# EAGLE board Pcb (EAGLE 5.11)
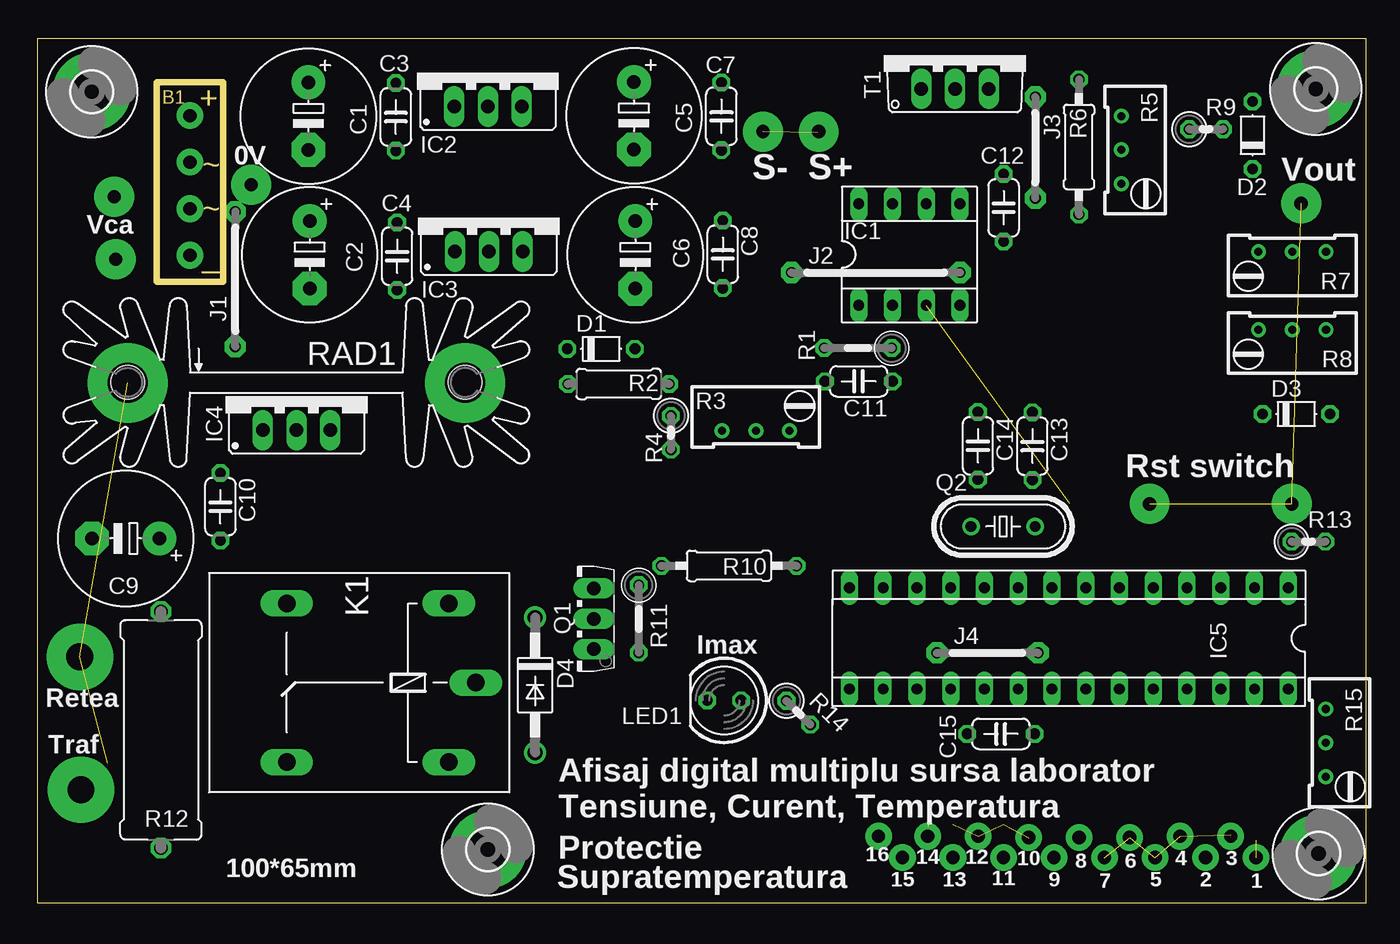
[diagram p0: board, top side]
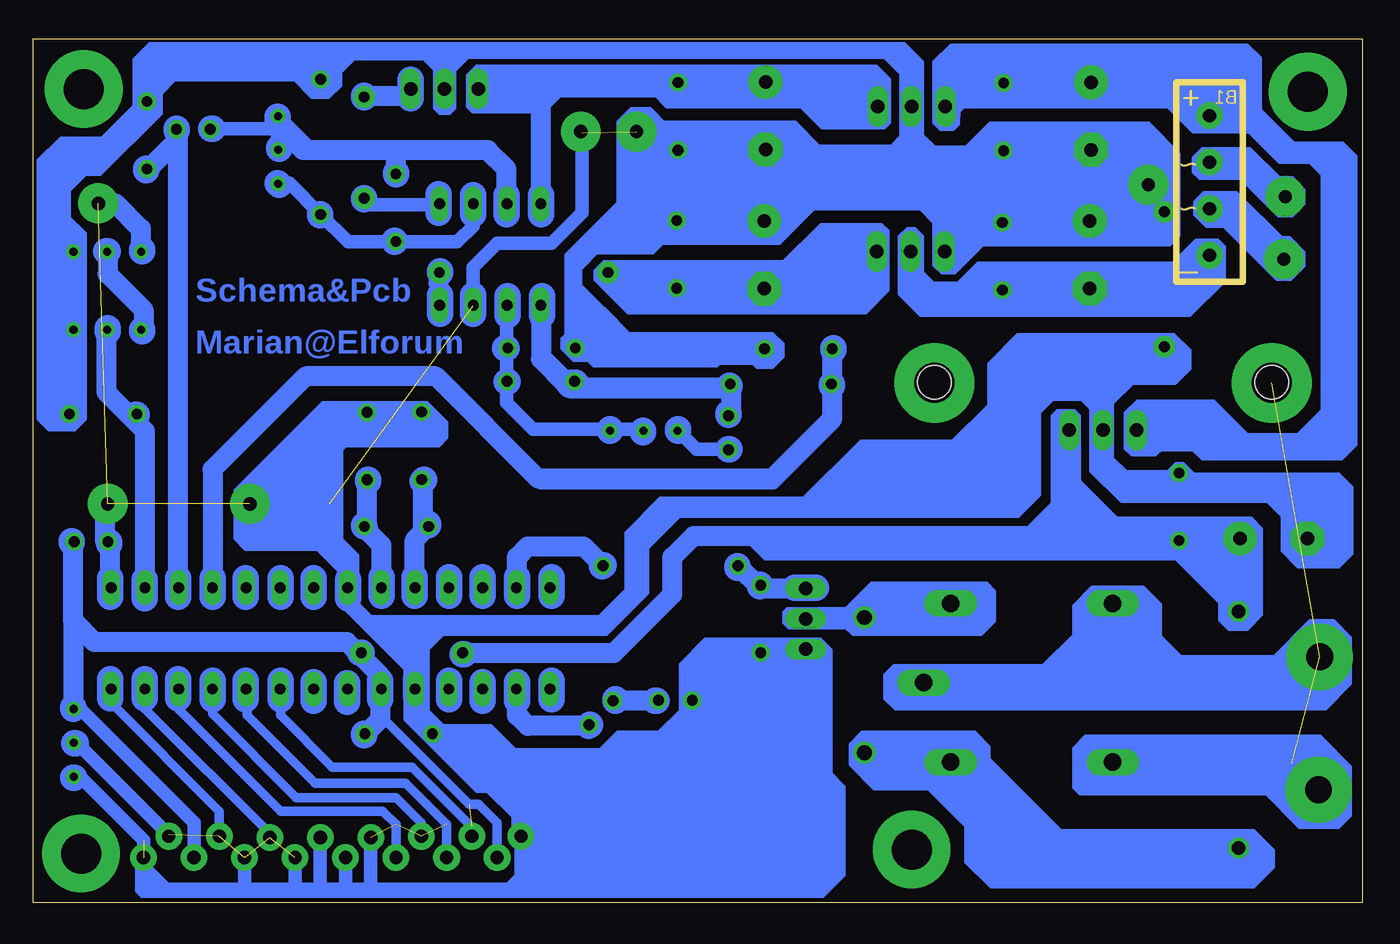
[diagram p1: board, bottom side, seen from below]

Size 100 x 65 mm. Coordinates in mm from the lower left corner, seen from the top.
Outline: 0,0 100,0 100,65 0,65 0,0
Outline: 9,61.7 14,61.7 14,46.7 9,46.7 9,61.7
Copper layers (1*16): Top 0.035mm / dielectric 1.5mm / Bottom 0.035mm
Design rules "default": minimum track width 10mil, minimum drill 24mil, track to track 8mil, track to pad 8mil, pad to pad 8mil, via to via 8mil, smd to smd 8mil, copper to edge 40mil, drill to drill 8mil, minimum pad ring 10mil, minimum via ring 8mil, stop-mask expansion 4mil, vias tented up to drill 0mil, thermal gap 10mil

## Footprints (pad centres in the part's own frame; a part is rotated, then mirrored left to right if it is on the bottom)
E5-10,5 = drill 1.016 pad 2.54 round: + -2.54,0 | drill 1.016 pad 2.54 octagon: - 2.54,0
C050-024X044 = drill 0.813 octagon: 1 -2.54,0; 2 2.54,0
D-5 = drill 0.813 octagon: A 2.54,0; C -2.54,0
DO41-10 = drill 1.118 round: A 5.08,0; C -5.08,0
3,0-PAD = drill 3 pad 5.842 round: B3,0 0,0
SOCKET-08 = drill 0.813 long: 1 -3.81,-3.81; 2 -1.27,-3.81; 3 1.27,-3.81; 4 3.81,-3.81; 5 3.81,3.81; 6 1.27,3.81; 7 -1.27,3.81; 8 -3.81,3.81
78XXS = drill 1.016 long: GND 0,-2.54; IN -2.54,-2.54; OUT 2.54,-2.54
79XXS = drill 1.016 long: GND -2.54,-2.54; IN 0,-2.54; OUT 2.54,-2.54
SOCKET-28-3 = drill 0.813 long: 1 -16.51,-3.81; 2 -13.97,-3.81; 3 -11.43,-3.81; 4 -8.89,-3.81; 5 -6.35,-3.81; 6 -3.81,-3.81; 7 -1.27,-3.81; 8 1.27,-3.81; 9 3.81,-3.81; 10 6.35,-3.81; 11 8.89,-3.81; 12 11.43,-3.81; 13 13.97,-3.81; 14 16.51,-3.81; 15 16.51,3.81; 16 13.97,3.81; 17 11.43,3.81; 18 8.89,3.81; 19 6.35,3.81; 20 3.81,3.81; 21 1.27,3.81; 22 -1.27,3.81; 23 -3.81,3.81; 24 -6.35,3.81; 25 -8.89,3.81; 26 -11.43,3.81; 27 -13.97,3.81; 28 -16.51,3.81
10 = drill 0.813 pad 1.6 octagon: 1 -5.08,0; 2 5.08,0
12 = drill 0.813 pad 1.6 octagon: 1 -6.35,0; 2 6.35,0
07 = drill 0.813 pad 1.6 octagon: 1 -3.81,0; 2 3.81,0
G5LE = drill 1.321 long: 1 -7.493,-5.969; 2 -7.493,5.969; O 4.699,5.969; P -9.525,0; S 4.699,-5.969
LED5MM = drill 0.813 octagon: A -1.27,0; K 1.27,0
TO126V = drill 1.016 long: 1 -2.286,-1.27; 2 0,-1.27; 3 2.286,-1.27
HC49/S = drill 0.813 round: 1 -2.413,0; 2 2.413,0
0207/5V = drill 0.813 octagon: 1 -2.54,0; 2 2.54,0
0207/7 = drill 0.813 octagon: 1 -3.81,0; 2 3.81,0
RTRIM64W = drill 0.61 round: 1 1.27,-2.54; 2 1.27,0; 3 1.27,2.54
0207/2V = drill 0.813 octagon: 1 -1.27,0; 2 1.27,0
0207/10 = drill 0.813 octagon: 1 -5.08,0; 2 5.08,0
0617/17 = drill 1.016 octagon: 1 -8.89,0; 2 8.89,0
SK104 = hole 2.54: -12.7,-0.762; 12.7,-0.762
TO220AV = drill 1.016 long: B -2.54,-2.54; C 0,-2.54; E 2.54,-2.54

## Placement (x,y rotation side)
C1  [E5-10,5]  20.4,59.17 270 top
C2  220u  [E5-10,5]  20.5,48.74 270 top
C3  220n  [C050-024X044]  26.98,59.11 270 top
C4  220n  [C050-024X044]  27.08,48.63 270 top
C5  100u  [E5-10,5]  44.9,59.2 270 top
C6  100u  [E5-10,5]  45,48.73 270 top
C7  100n  [C050-024X044]  51.48,59.15 270 top
C8  100n  [C050-024X044]  51.58,48.77 270 top
C9  100u  [E5-10,5]  6.66,27.4 180 top
C10  100n  [C050-024X044]  13.78,29.79 270 top
C11  1n  [C050-024X044]  61.81,39.22 180 top
C12  1n  [C050-024X044]  72.72,52.27 90 top
C13  22p  [C050-024X044]  74.88,34.35 270 top
C14  22p  [C050-024X044]  70.78,34.37 270 top
C15  470n  [C050-024X044]  72.51,12.7 180 top
D1  5V1  [D-5]  42.43,41.66 0 top
D2  5V1  [D-5]  91.44,57.73 90 top
D3  5V1  [D-5]  94.73,36.76 0 top
D4  1N4004  [DO41-10]  37.46,16.37 270 top
E$1  [3,0-PAD]  96.2,61.2 0 top
E$2  [3,0-PAD]  96.4,3.7 0 top
E$3  [3,0-PAD]  33.9,4 0 top
E$4  [3,0-PAD]  4.1,61 0 top
IC1  LM358  [SOCKET-08]  65.62,48.76 0 top
IC2  7808  [78XXS]  33.91,62.43 0 top
IC3  7908  [79XXS]  33.98,51.53 0 top
IC4  7805  [78XXS]  19.51,38.08 0 top
IC5  PIC16F876A  [SOCKET-28-3]  77.62,19.89 180 top
J1  [10]  14.9,46.9 90 top
J2  [12]  63.1,47.4 0 top
J3  [07]  75.1,56.8 270 top
J4  [07]  71.5,18.8 0 top
K1  3V  [G5LE]  23.47,16.55 180 top
LED1  [LED5MM]  51.69,15.22 180 top
Q1  BD139-16  [TO126V]  40.61,21.36 90 top
Q2  4Mhz  [HC49/S]  72.67,28.3 0 top
R1  1k  [0207/5V]  61.75,41.72 180 top
R2  470  [0207/7]  43.75,39.02 180 top
R3  20k  [RTRIM64W]  54.07,36.78 270 top
R4  1k  [0207/2V]  47.68,35.35 270 top
R5  5k  [RTRIM64W]  82.84,56.63 180 top
R6  1k  [0207/10]  78.38,56.85 270 top
R7  100k  [RTRIM64W]  94.43,47.7 90 top
R8  10k  [RTRIM64W]  94.43,41.84 90 top
R9  470  [0207/2V]  87.95,58.18 0 top
R10  1k  [0207/10]  52.05,25.34 180 top
R11  10k  [0207/5V]  45.26,21.35 270 top
R12  20R/3W  [0617/17]  9.31,13.01 90 top
R13  10k  [0207/2V]  95.65,27.16 0 top
R14  220  [0207/2V]  57.27,14.29 315 top
R15  1k  [RTRIM64W]  98.22,12.03 180 top
RAD1  [SK104]  19.5,39.9 0 top
T1  LM35DT  [TO220AV]  69.05,63.76 0 top

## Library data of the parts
C1-C15 R1-R11 R13-R15 = resistor
D1-D4 = diode
E$1-E$4 = holes
IC1 = ic-package
IC2-IC4 = v-reg
IC5 = ic-package; OC_FARNELL: unknown; OC_NEWARK: unknown
J1-J4 = jumper
K1 = relay; OC_FARNELL: unknown; OC_NEWARK: unknown
LED1 = led
Q1 = transistor-npn
Q2 = crystal; OC_FARNELL: 1667008; OC_NEWARK: unknown
R12 = resistor; OC_FARNELL: unknown; OC_NEWARK: unknown
RAD1 = heatsink
T1 = transistor-power

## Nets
N$15: R7.3
N$26: K1.1
S$106: C9.+

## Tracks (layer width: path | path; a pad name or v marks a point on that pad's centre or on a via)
S$1  (via drill 1 pad 2)
  other vias: 11.5,59.2
S$2
  Bottom 0.5: 12,56.6 12.6,56 12.6,55 12.2,54.6 9.1,54.6 6.3,51.8 5.3,51.8 4.5,52.6 4.5,53.6 5.3,54.4 6.3,54.4 8.5,56.6 12,56.6
S$3
  Bottom 0.5: 35.7,58.7 35.7,61.9 36.6,62.8 66.6,62.8 67.2,62.2 67.2,59.9 66.9,59.6 61.6,59.6 60.4,60.8 53.1,60.8 52.3,60 42.2,60 40.6,58.4 36,58.4 35.7,58.7
S$4  (via drill 1 pad 2)
  other vias: 11.5,48.7
S$5
  Bottom 0.5: 27,51.4 27.1,51.3
S$6  (via drill 2 pad 5)
  other vias: 3.3,8.5
S$7  (via drill 1 pad 2)
  other vias: 11.5,55.7
S$8
  Bottom 0.5: 32.3,46.5 33.2,47.4 33.2,50.1 33.7,50.6 34.2,50.6 34.7,50.1 34.7,45.8 33.2,44.3 13,44.3 10.5,46.8 10.5,49.3 10.9,49.7 12.5,49.7 14.2,48 28.9,48 30.4,46.5 32.3,46.5
S$9  (via drill 1 pad 3)
  other vias: 5.9,48.4
S$10  (via drill 1 pad 3)
  other vias: 5.8,53.1
S$11
  Bottom 0.5: 35.8,46.1 35.8,50.5 36.2,50.9 40.7,50.9 43.5,48.1 57,48.1 57.6,47.5 57.6,46.9 55.2,44.5 37.4,44.5 35.8,46.1
S$12
  Bottom 0.5: 55.2,54.5 55.2,53.3 59.8,48.7 59.8,42.7 60.1,42.4 60.1,41.7 59.3,40.9 58.2,40.9 57.8,40.5 48.6,40.5 48.4,40.7 45.8,40.7 45.5,40.4 44.4,40.4 43.7,41.1 43.7,42 44.4,42.7 55.2,42.7 57.1,44.6
S$13  (via drill 1 pad 2)
  other vias: 11.5,52.2
S$14
  Bottom 0.5: 12.5,51.8 12.5,52.7 11.9,53.3 9.5,53.3 6.1,49.9 5.5,49.9 4.5,48.9 4.5,47.9 5.4,47 6.4,47 10.4,51 11.7,51 12.5,51.8
S$15
  Bottom 0.5: 63.5,5 63.8,5.3 63.8,6.5 65.8,8.5 66.6,8.5 71.9,13.8 71.9,17.6 76.9,22.6 76.9,25 78.6,26.7 84,26.7 84.7,27.4 84.7,31 78.2,37.5 70.4,37.5 69,36.1 69,35 69.5,34.5 70.8,34.5 | 91.9,2.1 91.9,2.8 92.1,3 92.1,0.9 91.8,0.6 40.6,0.6 39.1,2.1 39.1,8.7 40.1,9.7 40.1,19 40.8,19.7 49.4,19.7 51.2,17.9 51.2,14.4 52.9,12.7 56,12.7 57.3,11.4 63.8,11.4 65.6,13.2 69.2,13.2 70.4,14.4 70.4,19.1 69.2,20.3 56.9,20.3 53.9,23.3 53.9,26.7 51.4,29.2 25.9,29.2 24.4,30.7 24.4,36.9 23.3,38 21.1,38 20.3,37.2 20.3,32.5 18.1,30.3 7.1,30.3 5.9,29.1 5.9,26.5 4.8,25.4 1.8,25.4 0.9,26.3 0.9,31.2 1.8,32.1 12.7,32.1 13.5,32.9 14,32.9 14.6,32.3 17.8,32.3 18.9,33.4 18.9,37.6 17.3,39.2 14.1,39.2 13.1,40.2 13.1,41.5 14.2,42.6 25.9,42.6 28,40.5 28,37.4 30.8,34.6 37.7,34.6 42,30.3 52.8,30.3 55.3,27.8 55.3,23.5 57.4,21.4 74.7,21.4 75.7,22.4 75.7,26.1 76.9,27.3 76.9,34.1 76.3,34.7 71,34.7 70.8,34.5 | 77,34.1 76.6,34.5 70.8,34.5
S$16
  Bottom 0.7: 86.5,16.1 86.5,14.2 80.2,7.9 72.7,7.9 70.8,6 70.8,5.1
S$17
  Bottom 1: 94.2,9.5 96.8,12.1
S$18
  Bottom 1: 45.3,18.7 45.2,18.8
S$19  (via drill 1 pad 3)
  other vias: 16.1,54
S$20  (via drill 1 pad 3)  (2 unrouted)
  Bottom 1: 94.3,27.1 94.4,27.2 v94.4,30 | 91.9,48.9 91.9,49.1 91.9,50.6 93.9,52.6 95.2,52.6 | 94.1,23.5 94.1,26.8 94.3,27 94.4,27.1
  Bottom 1.5: v95.1,52.6 93.8,52.6 91.9,50.7 91.9,49.1
  Bottom 2: 94.3,27.1 94.3,27
  other vias: 83.7,30
S$21
  Bottom 0.5: 29.2,12.7 37.6,12.7 38.4,11.9 38.4,10.4 36.7,8.7 32.6,8.7 29.7,5.8 29.7,3.1 27.9,1.3 8.2,1.3 6.8,2.7 6.8,3.9 8.2,5.3 22.7,5.3 28.2,10.8 28.2,11.7 29.2,12.7
S$22
  Bottom 0.5: 27.8,22.9 27.8,23.3 27.8,23.4 28.3,23.9 36.9,23.9 38.8,22 43.2,22 43.4,21.8 43.4,21.1 43.1,20.8 38.8,20.8 38.3,20.3 28.7,20.3 27.8,21.2 27.8,22.9
S$23
  Bottom 1: 69.4,45 69.4,47.4 69.5,47.5
  Bottom 2: 69.4,47.5 69.4,47.4
S$24
  Bottom 0.5: 21.6,22.3 20.3,23.6 16.5,23.6 15.3,22.4 15.3,20 13.7,18.4 6.6,18.4 3.9,21.1 2.2,21.1 1,19.9 1,16.5 2.8,14.7 35.1,14.7 35.8,15.4 35.8,17.1 35.2,17.7 24,17.7 21.6,20.1 21.6,22.3
S$25  (via drill 2 pad 5, 3 pad 6)  (2 unrouted)
  other vias: 6.8,39.1 3.2,18.5
S$26  (via drill 3 pad 6)
  other vias: 32.2,39.1
S$27
  Bottom 0.5: 6.2,55.8 8.5,58.1 12.7,58.1 14.6,60 30,60 30.5,59.5 30.5,58.6 30.8,58.3 31.7,58.3 32.1,58.7 32.1,63.2 30.9,64.4 8.7,64.4 7.8,63.5 7.8,59.6 5.2,57 1.5,57 0.6,56.1 0.6,34.5 1.6,33.5 12,33.5 12.7,34.2 15.2,34.2 15.6,33.8 17.3,33.8 17.7,34.2 17.7,36.8 16.9,37.6 11.2,37.6 8.7,35.1 4.8,35.1 2.9,37 2.9,54.8 3.9,55.8 6.2,55.8
S$28
  Bottom 1.5: 74.9,31.8 74.9,28.2 74.8,28.1
S$29
  Bottom 0.5: 22.1,35.5 22,35.4 22,31.8 18.7,28.5
S$30
  Bottom 1: 69.5,52.5 74.7,52.5 75.1,52.9 75.2,53
  Bottom 2: 75.1,52.9 75.1,53
S$31
  Bottom 0.5: 57.7,49.1 59.3,47.5 59.3,42.2 59.3,41.5 | 59.2,41.8 59.5,42.1 59.5,47.9 55.9,51.5 55.9,58.7 55,59.6 53.6,59.6 52.6,58.6 42.7,58.6 40.9,56.8 35.4,56.8 34.6,57.6 34.6,62.4 35.9,63.7 67.3,63.7 68.4,62.6 68.4,59.8 68.7,59.5 69.4,59.5 69.7,59.8 69.7,62.7 70.6,63.6 75.9,63.6 77,62.5 77,61.5 77.8,60.7 79,60.7 80.3,62 89.4,62 90.5,60.9 90.5,59.4 95,54.9 96.1,54.9 97.4,53.6 97.4,51.5 96.2,50.3 96.2,36.4 96.9,35.7 98.8,35.7 99.5,36.4 99.5,55.8 97.9,57.4 94.8,57.4 92.3,59.9 92.3,63.4 91.2,64.5 34.5,64.5 33.2,63.2 33.2,57.7 32.2,56.7 29.8,56.7 28,58.5 16.1,58.5 13.9,56.3 13.9,50.2 14.5,49.6 28.6,49.6 30.7,47.5 31.6,47.5 32.1,48 32.1,51.2 33.2,52.3 41.3,52.3 43.9,49.7 52.7,49.7 53.4,49 57.7,49
  Bottom 1: 59.2,46.3 59.2,41.8 59.2,41.6 | 57.6,49.4 59.2,47.8 59.2,46.3 | 45,41.6 48.7,41.6 54.5,41.6 59.2,46.3
  Bottom 1.5: 58.7,45 58.7,42.8 59.3,42.2 59.3,41.7 59.2,41.6 57.8,41.6 57.4,41.2 49.1,41.2 48.7,41.6 45.6,41.6 45.2,41.2 44.6,41.2 44.4,41.4 44.4,41.7 44.5,41.8 55.8,41.8 57.9,43.9 57.9,43 57,42.1 58.4,42.1 58.8,41.7 58.8,44.5 59.1,44.8
S$32
  Bottom 1.5: 70.7,31.8 70.7,31.7 70.7,28.2
  Bottom 2: 70.6,31.8 70.7,31.7
S$33
  Bottom 1.5: 61.8,52.6 61.8,61.2
S$34
  Bottom 1: 64.4,44.9 64.4,41.7 64.4,39.2 64.4,37.6 62.4,35.6 56.6,35.6 54.1,35.6 54,35.5
  Bottom 2: 64.4,41.7 64.5,41.7 | 64.3,39.2 64.4,39.2 | 56.6,35.5 56.6,35.6
S$35
  Bottom 1: 47.7,34.1 50.1,34.1 51.5,35.5 51.6,35.6
  Bottom 2: 51.5,35.5 51.5,35.6 | 47.7,34.1 47.6,34.1
S$37  (via drill 1 pad 2)  (4 unrouted)
  Bottom 0.7: 94.2,16.1 94.2,15.1 86,6.9 v86,5
  Bottom 1: 94.1,9.4 89.8,5.1 v89.8,5 | 80.3,1.2 80.3,3.3
  Bottom 1.676: v86,5 86,4.9 | 89.8,4.9 v89.8,5 | 80.3,3.3 v80.3,3.4
  other vias: 84.1,3.4 82.2,4.9
S$38
  Bottom 1: 47.7,36.8 47.7,38.9 47.5,39.1
  Bottom 2: 47.7,36.7 47.7,36.8
S$39
  Bottom 1: 72.7,56.1 72.7,56.4 72.8,56.5
  Bottom 1.5: 72.7,54.9 72.7,56.1
  Bottom 2: 72.7,54.8 72.7,54.9
S$40  (via drill 1 pad 3)  (2 unrouted)
  Bottom 0.5: 58.7,56.4 58.7,57.2 58.8,57.3 v58.8,58
  Bottom 1: v58.8,58 58.7,57.9 58.7,56.4 58.7,51.9 61,49.6 65.1,49.6 66.9,47.8 66.9,44.9
  other vias: 54.6,58
S$41
  Bottom 0.5: 61.8,41.4 61.8,41.2 | 61.8,43.7 61.8,44.8 61.9,44.9
  Bottom 1: 64.4,52.6 64.4,53.2 64.4,55.3 65.7,56.6 65.8,56.6 79,56.6 81.6,59.2 81.6,59.1 | 81.6,58.9 81.6,56.6 | 47.6,39 59.4,39 59.5,39.1 61.8,41.4 61.8,43.7 61.8,45
  Bottom 1.5: 64.4,52.5 64.4,55.2 65.8,56.6 79.7,56.6 81.4,58.3 | 61.7,44.9 61.7,43.8 61.8,43.7 61.8,40.9 59.9,39 59.9,38.9 59.7,38.7 47.7,38.7 47.6,38.8 47.5,38.9 47.5,36.8 47.8,36.5
  Bottom 2: 64.4,51.8 64.4,52.5 64.4,53.2 | 61.8,51.8 61.8,53.2 | 66.9,51.8 66.9,53.2 | 69.5,51.9 69.5,53.3 | 69.4,44.3 69.4,45.7 | 66.9,44.3 66.9,45.7 | 64.3,44.2 64.3,45.6 | 61.7,44.2 61.7,44.9 61.7,45.6 | 71.6,60.5 71.6,61.9 | 84,23 84,24.4 | 86.5,23 86.5,24.4 | 89.1,23 89.1,24.4 | 91.6,22.9 91.6,24.3 | 94.2,23 94.2,24.4 | 81.4,23 81.4,24.4 | 78.9,23 78.9,24.4 | 76.3,22.9 76.3,24.3 | 73.8,23.1 73.8,24.5 | 71.3,23.1 71.3,24.5 | 68.7,23.1 68.7,24.5 | 66.2,23.1 66.2,24.5 | 63.6,23.1 63.6,24.5 | 61,23.1 61,24.5 | 61,15.3 61,16.7 | 63.6,15.2 63.6,16.6 | 66.2,15.2 66.2,16.6 | 68.7,15.3 68.7,16.7 | 71.2,15.5 71.2,16.9 | 73.9,15.3 73.9,16.7 | 76.4,15.1 76.4,16.5 | 78.9,15.2 78.9,16.6 | 81.4,15.3 81.4,16.7 | 84,15.3 84,16.7 | 86.5,15.3 86.5,16.7 | 89.1,15.4 89.1,16.8 | 91.6,15.4 91.6,16.8 | 94.2,15.4 94.2,16.8 | 81.6,58.9 81.6,59.1 | 59.5,39.1 59.4,39.1 | 47.6,38.9 47.6,38.8
S$42
  Bottom 0.5: 21.6,8.7 21.6,11.6 20.8,12.4 3.2,12.4 1,10.2 1,6.6 1.8,5.8 4.7,5.8 7.2,8.3 21.2,8.3 21.6,8.7
S$43
  Bottom 0.5: 75.1,60.7 75.2,60.7
  Bottom 1.5: 75.1,60.7 72.1,60.7 71.6,61.2
  Bottom 2: 75.1,60.6 75.1,60.7
S$44
  Bottom 1: 66.9,52.5 66.9,50.9 68.1,49.7 72.8,49.7 76.3,49.7 78.4,51.8 80.7,54.1 81.5,54.1
  Bottom 2: 78.4,51.7 78.4,51.8 | 72.8,49.7 72.8,49.8
S$45
  Bottom 0.5: 51.5,51.5 51.6,51.4
S$46
  Bottom 1.5: 41.6,23.6 45.2,23.6 47,25.4
S$47
  Bottom 0.5: 59.4,41.8 59.3,41.7
S$48
  Bottom 1: 81.7,58.2 86.5,58.2 | 86.6,58.2 86.7,58.2
  Bottom 2: 86.6,58.2 86.5,58.2
S$49
  Bottom 0.5: 91.5,3.5 91.5,2.9 89.7,1.1
S$50
  Bottom 1: 84.1,1.4 84.1,3.3 84.1,3.4
  Bottom 1.676: 84.1,3.3 84,3.4
S$51
  Bottom 0.5: 91.3,2.4 91.3,2.3 90.3,1.3
S$52
  Bottom 1: 89.4,58.1 89.4,57 91.3,55.1
S$53
  Bottom 0.5: 91.7,1.7 91.7,1.5 91.9,1.3 91.9,1.1 91.5,0.7 91.5,1 91.3,1.2
S$55  (via drill 1 pad 2)
  Bottom 1: v87.9,3.4 87.9,6 96.7,14.8
  Bottom 1.676: 87.9,3.3 v87.9,3.4
S$56
  Bottom 1: 91.9,43.1 91.9,44.6 94.4,47.1 94.4,48.8
S$57
  Bottom 1.5: 58.2,13.3 62.8,13.3 63.6,14.1 63.6,16.3
  Bottom 2: 58.2,13.3 58.1,13.4
S$59
  Bottom 1.5: 24.4,60.9 30.3,60.9 31,60.2 31,59.1 31.1,59 31.4,59 | 31.4,59 31.5,59 31.5,62.7 30.7,63.5 9,63.5 8.7,63.2 8.7,59.5 5.6,56.4 | 5.6,56.4 3.3,56.4 | 3.3,56.4 1.9,56.4 1.2,55.7 1.2,35.1 2,34.3 11.7,34.3 12.4,35 15.4,35 15.8,34.6 16.9,34.6 17,34.5 17,36.5 16.6,36.9 11.7,36.9 9.6,34.8 11,34.8 12,35.8 16.7,35.8 16.8,35.7 10.8,35.7 9.5,34.4 4.4,34.4 2.4,36.4 | 2.1,36.7 2.1,34.9 2.4,34.6 2.4,36.4 | 2.4,36.4 2.1,36.7 | 2.1,36.7 2.1,55 3.3,56.2 3.3,56.4 | 5.6,56.4 5.8,56.4 8.4,59 12.6,59 14.4,60.8 31,60.8 31.1,60.9 31.1,59.3 31.4,59 | 31.4,59 31.4,61.2 30.4,62.2 9.7,62.2 9.7,60.2 9.8,60.1 12.4,60.1 13.7,61.4 11.2,61.4 10.7,60.9
S$60
  Bottom 1.5: 10.1,55.3 11.9,55.3 12,55.4 12,55.8 11.9,55.9 8.8,55.9 6.7,53.8 5.8,53.8 5.2,53.2 5.2,52.9 5.6,52.5 6,52.5 8.8,55.3 11.7,55.3 11.9,55.5
S$61
  Bottom 1: 73.9,23.6 73.9,27 75.2,28.3 75.1,28.4 75,28.5 75,31.7
  Bottom 1.5: 73.8,23.5 73.8,26.9 75.2,28.3
  Bottom 2: 75.1,28.3 75.1,28.4
S$62
  Bottom 1: 71.3,23.7 71.3,27.2 70.2,28.3
S$63
  Bottom 1: 70.8,31.7 70.8,28.8 70.3,28.3
  Bottom 1.5: 71.3,23.6 71.3,27.3 70.3,28.3
S$64  (via drill 1 pad 2)  (1 unrouted)
  Bottom 1: 97,9.5 96.5,9.5 91.7,4.7 v91.7,3.4 | 91.7,3.3 91.7,1.8 90.9,1 64.2,1 63.3,1.9 v63.3,5 63.2,4.9
  Bottom 1.676: 91.7,3.3 v91.7,3.4
S$65
  Bottom 1: 73.8,16 73.8,13.7 74.8,12.7 75,12.7 | 75.1,12.7 75.2,12.7 | 75.3,18.7 75.4,18.8 76.4,19.8 95.5,19.8 97,21.3 | 97,21.3 97,21.6 | 97,21.3 97,21.2 97,14.7 | 97,14.6 97,14.5 | 73.8,16.1 73.8,17.3 75.3,18.8
  Bottom 1.5: 75,12.7 73.9,13.8 73.9,17.1 76.4,19.6 95.4,19.6 97,21.2 | 97,21.2 97,21.6 97,27.1 96.9,27.2 | 97,21.2 97,14.9 96.7,14.6
  Bottom 1.676: 75.1,12.7 75,12.7
  Bottom 2: 97,14.6 97,14.7 | 75.1,12.7 75.1,12.6 | 75.4,18.8 75.3,18.8
S$66
  Bottom 0.7: 91.6,16 91.6,14.6 82.1,5.1
S$67  (via drill 1 pad 2)  (3 unrouted)
  Bottom 0.7: 84,16.1 83.9,16 83.9,14.1 78.8,9 72,9 68.9,5.9 v68.9,3.4 | v72.7,3.4 72.7,5.9 73.7,6.9 81.4,6.9 89,14.5 89,16.2
  Bottom 1: 74.6,1.3 v74.6,4.9
  Bottom 1.676: v74.6,4.9 74.6,5 | 72.7,3.3 v72.7,3.4 | 70.8,4.9 v70.8,5 | 69,3.4 v68.9,3.4
S$68
  Bottom 1: 57.2,25.2 57.2,25.3 57.2,25.4 58.5,26.7 62.6,26.7 63.6,25.7 63.6,23.7 63.6,23.6
  Bottom 1.5: 63.6,23.7 63.6,26 62.8,26.8 58.6,26.8 57.1,25.3
  Bottom 2: 57.1,25.4 57.2,25.3
S$69
  Bottom 1: 47,25.3 45.5,23.8 45.3,23.8 41.8,23.8 41.7,23.7
  Bottom 2: 47,25.2 47,25.3 | 45.3,23.8 45.3,23.9
S$70
  Bottom 1: 9.4,21.8 9.4,27.3
S$71
  Bottom 1: 45.1,19 45.2,18.9
S$72  (via drill 1 pad 2)
  Bottom 1: 76.5,1.4 76.5,3.3
  Bottom 1.676: 76.5,3.3 v76.5,3.4
S$73
  Bottom 1: 58.2,13.4 62.5,13.4 63.6,14.5 63.6,16.1
S$74
  Bottom 1.5: 12,52.3 11.8,52.3 11.6,52.5 9.7,52.5 6.4,49.2 5.9,49.2 5.3,48.6 5.3,48.2 5.8,47.7 6.1,47.7 10.1,51.7 11.4,51.7 11.6,51.9
S$75
  Bottom 1: 35.1,63.9 35.3,63.9 35.4,64 67.8,64 | 67.8,64 69,62.8 69,59.9 69.2,59.9 69.2,63 70.2,64 67.8,64 | 67.8,64 67.7,64.1 68.6,64.1 69.1,63.6 69.7,63.6 70.2,64.1 76.2,64.1 76.3,64 | 76.4,63.9 77.5,62.8 77.5,61.5 77.9,61.1 78.7,61.1 80.2,62.6 89.6,62.6 91.2,61 91.2,59.6 95.4,55.4 96.3,55.4 98,53.7 98,51.2 96.7,49.9 96.7,36.6 97.2,36.1 98.5,36.1 99,36.6 99,55.5 97.6,56.9 94.6,56.9 91.7,59.8 91.7,63.2 91,63.9 76.4,63.9 | 76.4,63.9 76.3,64 | 76.3,64 77.8,64 78.1,63.7 78.1,61.6 78,61.5 78.2,61.5 79.9,63.2 78.9,63.2 78.8,63.1 78.8,62.6 78.3,62.1
  Bottom 1.5: 15,53.6 15,53.1 14.7,52.8 14.7,50.6 14.9,50.4 29,50.4 31.1,48.3 31.4,48.3 31.4,51.5 32.9,53 41.7,53 44.3,50.4 53.2,50.4 53.8,49.8 56.7,49.8 56.8,49.7 56.6,49.7 55,51.3 55,58.5 54.6,58.9 54.1,58.9 53.1,57.9 43.2,57.9 41.4,56.1 35,56.1 33.9,57.2 33.9,62.7 35.1,63.9
S$76
  Bottom 1: 52.9,15.2 53.1,15.2 | 56.2,15.2 56.3,15.2
  Bottom 1.5: 53.2,15.2 56.2,15.2 56.4,15.2
  Bottom 2: 56.2,15.2 56.2,15.3 | 53.2,15.2 53.1,15.2
S$77
  Bottom 1: 79.8,63.3 90.3,63.3 90.5,63.1 | 90.5,63.1 90.9,62.7 90.9,62.1 91.1,61.9 91,61.9 90.3,62.6 90.3,62.9 90.5,63.1 | 90.5,63.1 90.7,63.1 90.8,63 90.8,60.4 95,56.2 97.3,56.2 98.2,55.3 98.2,54.3 98.3,54.2 98.1,54.2 96.6,55.7
S$79
  Bottom 1: 92.6,36.7 92.3,36.7 | 92.6,36.7 94.5,38.6 94.5,42.9 94.5,43.1 | 91.6,23.6 91.6,35.5 91.6,35.7 92.6,36.7
  Bottom 1.5: 94.5,42.9 94.5,38.4 91.6,35.5 91.6,23.5
  Bottom 2: 92.3,36.7 92.2,36.7
S$80
  Bottom 1: 89.3,58.2 89.1,58 89.1,23.7
S$81
  Bottom 1: 39.9,38.9 39.9,36 44.3,31.6 61.8,31.6 69.7,39.5 79.4,39.5 86.5,32.4 86.5,23.7 | 39.9,41.5 39.9,41.7
  Bottom 1.5: 39.9,41.5 39.9,39 | 39.9,38.9 39.9,36.4 44.4,31.9 62,31.9 69.7,39.6 79.5,39.6 86.5,32.6 86.5,23.5
  Bottom 2: 39.9,38.9 39.9,39
S$83
  Bottom 1: 98.5,51 98.5,50.4 97.4,49.3 97.4,37.1 97.6,36.9 98.1,36.9 98.1,49.1 98.4,49.4
S$84  (via drill 1 pad 2)  (1 unrouted)
  Bottom 0.7: 81.4,16.1 81.4,14.1 77.5,10.2 71.5,10.2 67,5.7 v67,5 | 65.1,3.5 65.1,6 66.5,7.4 67.2,7.4 73.7,13.9
  Bottom 1.676: 66.9,5 v67,5 | v65.1,3.4 65.1,3.5
S$85  (via drill 1 pad 2)
  Bottom 1: 78.4,1.5 78.4,4.8
  Bottom 1.676: 78.4,4.8 v78.4,4.9
S$86
  Bottom 1.5: 14.5,51.6 14.5,55.7 16.4,57.6 27.8,57.6 29.3,56.1 32.7,56.1 33.3,56.7
S$87
  Bottom 3: 54.5,50.3 54.5,50.4 53.4,51.5 53.4,56.4 54,57 44.3,57 42.1,54.8 28.1,54.8 27,55.9 17.1,55.9 16.3,55.1 16.3,53.9 | 16.3,53.9 16.3,52.1 16.1,51.9 28.4,51.9 30.3,50 30.3,51.7 31.4,52.8 16.4,52.8 16.1,53.1 16.1,53.7 16.3,53.9 | 16.3,53.9 43.6,53.9 45.7,51.8 52.2,51.8 52.2,54.7 43.6,54.7 43.2,55.1 43.2,54.9 43.9,54.2 52.7,54.2 53.1,53.8
S$88
  Bottom 1.5: 59.1,48.4 59.1,48.5 56,51.6
S$89
  Bottom 1.5: 23.1,46.4 23.1,47 23.2,47.1 28.7,47.1 30.1,45.7 32.8,45.7 34,46.9 | 34,46.9 34,50 | 34,46.9 34,46.1 32.9,45 13.3,45 11.3,47 11.3,48.9 11.4,49 12.2,49 14,47.2 27.8,47.2 28.9,46.1 14,46.1 11.9,48.2
S$90
  Bottom 1.5: 42.2,45.2 37.8,45.2 36.5,46.5 36.5,50 36.7,50.2 40.4,50.2 43.3,47.3 56.8,47.3 | 56.9,47.3 56.8,47.3 | 56.8,47.3 56.6,47.1 55.9,46.4 | 55.9,46.4 54.9,45.4 38.9,45.4 37.5,46.8 37.5,48.7 37.3,48.9 40.6,48.9 43.1,46.4 55.9,46.4
S$91
  Bottom 1.5: 43.4,46.1 41.7,46.1 39.9,47.9 38.5,47.9 38.5,47.6 40,46.1
S$92
  Bottom 1.5: 64.9,61.1 66.5,61.1 66.6,61 66.6,60.3 62,60.3 60.8,61.5 52.6,61.5 52,60.9 41.8,60.9 41.4,60.5 | 41.1,60.2 40.2,59.3 36.5,59.3 36.4,59.2 36.4,61.6 36.9,62.1 66.2,62.1 66.5,61.8 66.5,61 | 66.5,60.4 66.5,61 | 66.5,61 66.3,61.2 61.9,61.2 61.6,61.5 61.5,61.5 61.3,61.7 37.8,61.7 37,60.9 37,60.3 36.9,60.2 41.1,60.2 | 41.1,60.2 41.4,60.5 | 41.4,60.5 36.8,60.5 36.5,60.2 36.5,60.6 36.8,60.9 43.2,60.9 43.5,61.2
S$93
  Bottom 1.5: 3.9,28.4 4.9,28.4 5,28.3 5,26.7 4.5,26.2 2.3,26.2 1.8,26.7 1.8,30.9 2.1,31.2 5.8,31.2 6.3,30.7 6.3,30.6 5.2,29.5 5.2,27.3 4.7,26.8 2.9,26.8 2.9,30 2.7,30.2 4.8,30.2 5.1,30.5 5.1,29.7 4.8,29.4 3.9,29.4 3.8,29.3 3.8,27.6 3.7,27.5
S$94
  Bottom 1.5: 5.4,31 6,31 6.3,31.3 6.7,31.3 6.8,31.2 17.9,31.2 19.6,32.9 19.6,37.5 20.4,38.3
S$95
  Bottom 1.5: 18,31.6 14.4,31.6 13.8,32.2 13.3,31.7
S$96
  Bottom 1.016: 41.1,29.9 41.6,29.9 41.7,29.8 52.4,29.8 54.6,27.6 54.6,23.5 57.2,20.9 74.6,20.9 76.4,22.7 76.4,22.8 | 76.4,25.2 76.4,26.1 77.3,27 78.3,27 78.4,27.1 78.3,27.1 76.4,25.2 | 76.4,25.2 76.4,22.8 | 76.4,22.8 71.2,17.6 71.2,14.1 68.6,11.5 68.6,12.4 68.4,12.6 69.2,12.6 70.8,14.2 70.8,19.4 69.7,20.5 73.2,20.5 73.2,20.3 71.4,18.5 71.4,19.7 71.2,19.9 72.1,19.9 | 72.4,19.9 72.1,19.9 | 72.1,19.9 71.3,19.1
  Bottom 1.5: 19.7,38.1 19.6,38.1 17.7,40 14.4,40 13.9,40.5 13.9,41.2 14.5,41.8 25.5,41.8 27.1,40.2 27.1,37 30.3,33.8 37.2,33.8 41.1,29.9
S$97
  Bottom 1.016: 54.2,26.9 54.2,27 51.8,29.4
S$98
  Bottom 1.5: 39.2,30.6 40,29.8 26.5,29.8 25.2,31.1 25.2,37.2 23.6,38.8 20.1,38.8 20,38.7
S$99
  Bottom 3: 14.5,41 24,41 25.5,39.5 19.7,39.5 19,40.2 24.5,40.2 26.5,38.2 26.5,32.3 27.1,31.7 37.4,31.7 38.3,30.8 38.3,31.3 37,32.6 29.2,32.6 27.5,34.3
S$100
  Bottom 1.5: 78.7,28.4 78.7,27.7 78.8,27.6 83.7,27.6 83.9,27.8 83.9,30.6 77.8,36.7 70.7,36.7 69.8,35.8 69.8,35.3 76.8,35.3 77.6,34.5 77.6,27.1 77.4,26.9 77.4,27.7 78.1,28.4
S$101
  Bottom 3: 78.4,28.7 82.3,28.7 82.4,28.6 82.4,30.6 77.3,35.7
S$102
  Bottom 3: 78.8,33.8 78.8,30 79.5,29.3 81.3,29.3 82,30 81.5,30 78.4,33.1
S$103
  Bottom 1.5: 68.2,11.7 68.2,12.3 68.1,12.4 66,12.4 64.4,10.8 57,10.8 55.8,12 52.3,12 50.3,14 50.3,17.7 49.2,18.8 41.1,18.8 40.9,18.6 40.9,9.2 39.9,8.2 39.9,2.5 41,1.4 63,1.4 63.1,1.3
S$104
  Bottom 1.5: 62.6,2.2 62.6,5.2 63.1,5.7 63.1,7 65.2,9.1 66.2,9.1 66.4,9.3 66.4,9.5 68,11.1
S$105
  Bottom 3: 67.5,11.4 66,11.4 61.5,6.9 61.5,3 60.9,2.4 42.8,2.4 41.7,3.5 41.7,7.2 42.6,8.1 42.6,17 42.5,17.1 48.1,17.1 48.5,16.7 48.5,13.4 51.9,10 55.2,10 55.9,9.3 60.4,9.3 | 61.9,9.3 60.4,9.3 | 60.4,9.3 58.9,7.8 58.9,4.9 59.1,4.7 44.1,4.7 44,4.8 44,5.7 45.3,7 45.3,14.5 45,14.8 46,14.8 46.1,14.9 46.1,8.3 47.1,7.3 56.1,7.3 56.5,6.9 56.5,7.8 56.4,7.9 48.4,7.9 47.5,8.8 47.5,11 47.7,11.2 47.9,11.2 50.1,9 61.5,9 61.6,9.1
S$106
  Bottom 0.5: 22,35.6 21.4,35.6 | 21.4,35.6 21.4,36.6 21.7,36.9 22.9,36.9 23.2,36.6 23.2,30 25.6,27.6 | 21.4,35.6 21.4,31.7 18.5,28.8 | 18.5,28.8 18.3,28.6 | 18.5,28.8 8.4,28.8 7.7,28.1 7.7,21.7 8.7,20.7 10,20.7 10.6,21.3 10.6,22.6 14,26 44.9,26 46.1,27.2
  Bottom 1: 67.8,18.8 67.6,18.8 56.2,18.8 52,23 52,25.9 50.3,27.6 50.2,27.7 24.4,27.7 18.1,27.7 | C9.+ 12.7,27.4 17.8,27.4 18.1,27.7 | 18.1,27.7 22,31.6 22,35.5
  Bottom 1.5: 45,27.5 45,27.2 44.6,26.8 13.6,26.8 9.9,23.1 9.9,21.7 9.6,21.4 9.1,21.4 8.5,22 8.5,27.7 8.8,28 18.9,28 22.1,31.2 22.1,36.3 22.5,36.3 22.6,36.2 22.6,29.5 24.4,27.7 23.5,27.7 21.9,29.3 21.9,28.4 20.3,28.4 20.2,28.3 20.8,28.3 21.4,28.9 | 67.6,18.9 67.6,18.8 56.3,18.8 51.9,23.2 51.9,26 50.3,27.6 25.6,27.6 18.3,27.6 | 12.7,27.4 12.7,27.3 9.6,24.2 9.6,26.7 9.9,27 11.3,27 11.3,26.9 10.3,25.9
S$107
  Bottom 1.5: 28.4,22.5 28.4,21.8 29.1,21.1 38,21.1 38.3,21.4 38.4,21.4 | 42.9,21.4 38.4,21.4 | 38.4,21.4 36.7,23.1 28.5,23.1 28.5,22.4 28.6,22.3 37.2,22.3 38,21.5 29,21.5
S$108
  Bottom 1.5: 32.2,16.9 34.9,16.9 35.1,16.7 35.1,15.9 34.7,15.5 3.1,15.5 1.9,16.7 1.9,19.6 2.6,20.3 3.7,20.3 6.3,17.7 14.1,17.7 15.9,19.5 15.9,21.8 16.9,22.8 20.1,22.8 20.9,22 20.9,19.7 23.9,16.7 24.2,16.7 24.4,16.9 34.8,16.9 34.9,16.8 34.9,16.3 22.5,16.3 22.3,16.5
S$109
  Bottom 3: 22.7,16.5 21.4,16.5 19.4,18.5 19.4,21.2 19.5,21.3 17.8,21.3 17.2,20.7 17.2,18.3 15.5,16.6 4.7,16.6 3.2,18.1 3.2,19.5 3.1,19.6 3.1,17.8 4.3,16.6 19.7,16.6 19.9,16.8
S$110
  Bottom 1.5: 15.1,9.8 15.1,9.2 20.9,9.2 20.9,11.1 20.4,11.6 3.5,11.6 1.8,9.9 1.8,7 2.3,6.5 4.3,6.5 6.8,9 19.2,9 19.6,9.4
S$111
  Bottom 3: 19.8,10.3 4.8,10.3 3.5,9 3.5,8.2 3.4,8.1 4.2,8.1 6.3,10.2 19.3,10.2 19.6,10.5
S$112
  Bottom 1.5: 34.1,11.4 36.5,11.4 37,11.9 37.3,11.9 37.6,11.6 37.6,10.8 36.3,9.5 32.3,9.5 28.8,6 28.8,3.4 27.4,2 8.6,2 7.6,3 7.6,3.7 8.4,4.5 23.1,4.5 28.9,10.3 28.9,11.4 29.5,12 37.1,12 37.1,11.1 37,11 37,10.8 36.5,10.3 29.5,10.3 29.4,10.2 29.4,11 37.4,11 36.8,10.4 29.4,10.4 29.3,10.3 31.8,10.3 32,10.1 31.6,10.1 29,10.1
  Bottom 3: 31.6,10.1 30.4,10.1 27.3,7 27.3,4.5 26.5,3.7 24.4,3.7 | 8.8,3.7 24.4,3.7 | 24.4,3.7 27.9,7.2
S$113
  Bottom 1.5: 89.1,23.6 89.1,58.1 89.2,58.2 | 89.2,58.1 89.2,57.3 91.3,55.2
  Bottom 2: 89.2,58.1 89.2,58.2
S$114
  Bottom 1.5: 94.4,49 94.4,47.3 91.7,44.6 91.7,43.1
  Bottom 2: 94.5,49 94.4,49
S$115
  Bottom 1.5: 94.2,23.5 94.2,26.8 94.6,27.2 94.6,29.9
S$116
  Bottom 1.5: 69.5,47.3 69.5,46.6
S$117
  Bottom 2: 97,9.4 96.9,9.4
S$118
  Bottom 2: 96.9,12 96.8,12
S$119
  Bottom 2: 97.1,27.2 97.1,27.1
S$120
  Bottom 2: 94.4,43.2 94.4,43
S$121
  Bottom 2: 91.8,43.1 91.8,43
S$122
  Bottom 2: 91.8,49.1 91.8,49
S$123
  Bottom 2: 91.5,55.1 91.5,55.2
S$124
  Bottom 2: 81.6,54.1 81.5,54
S$125
  Bottom 2: 81.5,56.7 81.5,56.8
S$126
  Bottom 2: 74.8,31.8 74.8,31.7
S$127
  Bottom 1.676: 82.3,4.8 82.2,4.8
S$128
  Bottom 1.676: 63.3,5.2 63.3,5.1 63.4,5
S$129
  Bottom 2: 67.7,18.7 67.6,18.7
S$130
  Bottom 2: 70.3,28.4 70.3,28.5
S$131
  Bottom 2: 42.7,23.7 41.1,23.7
S$132
  Bottom 2: 59.3,39.1 59.2,39.1
S$133
  Bottom 2: 54.1,35.4 54.1,35.5
S$134
  Bottom 2: 39.8,41.6 39.8,41.7

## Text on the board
Bottom: Schema&Pcb | Marian@Elforum
Dimension: B1 | + | ~ | ~ | _
tNames: 0V | S- | S+ | Vout | Vca | Rst switch | Imax | Retea | Traf | Afisaj digital multiplu sursa laborator | Tensiune, Curent, Temperatura | Protectie | 16 | 14 | 12 | 10 | 8 | 6 | 4 | 3 | 100*65mm | Supratemperatura | 15 | 13 | 11 | 9 | 7 | 5 | 2 | 1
